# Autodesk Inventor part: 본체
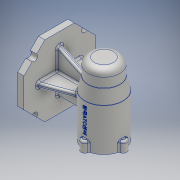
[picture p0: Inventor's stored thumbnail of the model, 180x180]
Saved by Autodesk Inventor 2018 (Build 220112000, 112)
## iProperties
Created: 2019-12
Part Number: 본체
Material: 알루미늄 6061
Document SubType Name: Modeling
Designer: Administrator
Density: 2.7 g/cm^3
Appearance: 알루미늄 - 평지
Mass: 726.009 g
Surface Area: 714.36 cm^2
Volume: 268.892 cm^3
Author: Administrator
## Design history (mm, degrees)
sketch "스케치1" dims "d0" = 112
  geometry: L1 (56, -23.196)-(23.196, -56); L2 (23.196, -56)-(-23.196, -56); L3 (-23.196, -56)-(-56, -23.196); L4 (-56, -23.196)-(-56, 23.196); L5 (-56, 23.196)-(-23.196, 56); L6 (-23.196, 56)-(23.196, 56); L7 (23.196, 56)-(56, 23.196); L8 (56, 23.196)-(56, -23.196); 5 further points
  constraints: 16 end point, 3 coincident, 1 horizontal alignment, 1 midpoint, 19 other
extrude "돌출1" new body sketch "스케치1" distance "d1" = 10; taper "d2" = 0 deg
sketch "스케치3"
  geometry: L1 (0, 0)-(-80, 0); L2 (-80, 0)-(-80, -56); L3 (-80, -56)-(-110, -56); L4 (-110, -56)-(-110, -40); L5 (-110, -40)-(-80, -40); L6 (-80, -40)-(-80, -56); L7 (-80, -40)-(-110, -40); L8 (-110, -40)-(-110, 11); L9 (-110, 11)-(-80, 11); L10 (-80, 11)-(-80, -40); L11 (-80, 0)-(-80, 56); L12 (-80, 56)-(-105, 56); L13 (-105, 56)-(-105, 31); L14 (-105, 31)-(-80, 31); L15 (-80, 31)-(-80, 56); L16 (-105, 31)-(-110, 11); L17 (-80, 31)-(-80, 11)
  constraints: 34 end point, 6 parallel, 4 horizontal, 3 perpendicular, 2 vertical, 1 point on line
  dimensions: "d4" = 56 distance of L1.end L2.end; "d5" = 30 distance of L4.end L5.end; "d6" = 16 distance of L3.end L4.end; "d7" = 30 distance of L8.end L9.end; "d8" = 51 distance of L7.end L8.end; "d9" = 56 distance of L1.end L11.end; "d10" = 25 distance of L14.end L13.end; "d11" = 25 distance of L13.end L12.end
revolve "회전1" sketch "스케치3" stored, may be unused: angle "d12" = 90 deg
sketch "스케치4"
  geometry: L1 (0, 0)-(0, 30); L2 (0, 30)-(0, -30); L3 (0, 0)-(-32.316, 0); L4 (-32.316, 0)-(30, 0); L5 (0, 0)-(-30, 0); L6 (-30, 0)-(30, 0); L7 (0, 0)-(-31.297, 0); C1 r 25 at (0, 0) reference; C2 r 6 at (-30, 0); C3 r 6 at (0, -30); C4 r 6 at (0, 30); C5 r 6 at (30, 0); A1 r 30 centre (0, 0) between (30, 0) and (0, 30); A2 r 30 centre (0, 0) between (0, 30) and (0, -30) reference; 1 further point
  constraints: 14 end point, 5 centre point, 5 point on circle, 4 coincident, 1 horizontal, 1 point on line, 1 vertical
  dimensions: "d13" = 12 diameter of C2; "d14" = 12 diameter of C3; "d15" = 12 diameter of C4; "d16" = 12 diameter of C5
extrude "돌출2" join sketch "스케치4" distance "d17" = 16; taper "d18" = 0 deg
sketch "스케치5"
  geometry: L1 (-10, -56)-(-10, -23.196) reference; L2 (-10, -56)-(-10, -31); L3 (-10, -31)-(-69.314, -31); L4 (-10, 23.196)-(-10, 56) reference; L5 (-10, 56)-(-10, 38); L6 (-10, 38)-(-71.6, 9.275); L7 (-71.6, 9.275)-(-69.314, -31); L8 (-10, -31)-(-10, 38); 1 further point
  constraints: 12 end point, 2 point on line, 1 collinear, 1 perpendicular
  dimensions: "d19" = 25 distance of L1.start L2.end; "d20" = 18 distance of L4.end L5.end; "d21" = 115 deg angle of L5 L6
extrude "돌출3" join sketch "스케치5" stored distance "d22" = 8; taper "d23" = 0 deg
node "작업 평면1"
sketch "스케치6"
  geometry: L1 (10, 79.196)-(10, 59.196); L2 (10, 46.392)-(10, 79.196) reference; L3 (10, -32.804)-(10, 0) reference; L4 (10, -32.804)-(10, -12.804); L5 (10, -12.804)-(64.681, 7.098); L6 (10, 59.196)-(75.807, 35.244); L7 (75.807, 35.244)-(64.681, 7.098); L8 (10, 59.196)-(10, -12.804); 1 further point
  constraints: 12 end point, 2 point on line, 1 collinear
  dimensions: "d24" = 20 distance of L1.start L1.end; "d25" = 20 distance of L3.start L4.end; "d26" = 110 deg angle of L4 L5; "d27" = 110 deg angle of L6 L1
extrude "돌출4" join sketch "스케치6" stored distance "d28" = 8; taper "d29" = 0 deg
sketch "스케치7"
  geometry: L1 (0, 0)-(-39.598, 39.598); L2 (0, 0)-(62.448, 0); L3 (0, 0)-(39.598, 39.598); L4 (0, 0)-(80.362, 0); L5 (0, 0)-(39.598, -39.598); L6 (0, 0)-(85.885, 0); L7 (0, 0)-(-39.598, -39.598); L8 (0, 0)-(72.456, 0); L9 (-56, 23.196)-(-23.196, 56) reference; L10 (-56, 23.196)-(-23.196, 56); L11 (-23.196, 56)-(23.196, 56); L12 (23.196, 56)-(56, 23.196); L13 (56, 23.196)-(56, -23.196); L14 (56, -23.196)-(23.196, -56); L15 (23.196, -56)-(-23.196, -56); L16 (-23.196, -56)-(-56, -23.196); L17 (-56, -23.196)-(-56, 23.196); 1 further point
  constraints: 32 end point, 4 horizontal, 4 midpoint, 1 coincident, 17 other
  dimensions: "d30" = 135 deg angle of L2 L1; "d31" = 45 deg angle of L4 L3; "d32" = 45 deg angle of L5 L6; "d33" = 135 deg angle of L7 L8
hole "구멍1" sketch "스케치7" at (39.598, 39.598), (-39.598, -39.598), (39.598, -39.598), (-39.598, 39.598) diameter "d34" = 10; stored, may be unused: countersink angle "d38" = 90 deg, drill point angle "d40" = 118 deg; dims "d35" = 6, "d36" = 4, "d37" = 2, "d39" = 10
sketch "스케치8"
  geometry: L1 (-74, -56)-(-86, -56) reference; L2 (-80, -56)-(-101, -56); L3 (-101, -56)-(-101, -41); L4 (-101, -41)-(-80, -41); L5 (-80, -41)-(-80, -56); L6 (-80, -41)-(-104, -41); L7 (-104, -41)-(-104, 13); L8 (-104, 13)-(-80, 13); L9 (-80, 13)-(-80, -41); L10 (-80, 13)-(-101, 13); L11 (-101, 13)-(-101, 25); L12 (-101, 25)-(-80, 25); L13 (-80, 25)-(-80, 13); L14 (-80, 25)-(-97.5, 25); L15 (-97.5, 25)-(-97.5, 43); L16 (-97.5, 43)-(-80, 43); L17 (-80, 43)-(-80, 25); L18 (-80, 43)-(-96, 43); L19 (-96, 43)-(-96, 47); L20 (-96, 47)-(-80, 47); L21 (-80, 47)-(-80, 43); L22 (-80, 47)-(-90.5, 47); L23 (-90.5, 47)-(-90.5, 50); L24 (-90.5, 50)-(-80, 50); L25 (-80, 50)-(-80, 47); 3 further points
  constraints: 48 end point, 12 parallel, 6 horizontal, 6 perpendicular, 1 midpoint
  dimensions: "d41" = 21 distance of L3.end L4.end; "d42" = 15 distance of L2.end L3.end; "d43" = 24 distance of L7.end L8.end; "d44" = 54 distance of L6.end L7.end; "d45" = 21 distance of L11.end L12.end; "d46" = 12 distance of L10.end L11.end; "d47" = 17.5 distance of L15.end L16.end; "d48" = 18 distance of L14.end L15.end; "d49" = 16 distance of L19.end L20.end; "d50" = 4 distance of L18.end L19.end; "d51" = 10.5 distance of L23.end L24.end; "d52" = 3 distance of L22.end L23.end
revolve "회전2" sketch "스케치8" stored, may be unused: angle "d53" = 90 deg
fillet "모깎기1" dims "d54" = 3
fillet "모깎기2" dims "d55" = 0.3
fillet "모깎기3" dims "d56" = 3
chamfer "모따기1" distance "d57" = 1; stored, may be unused: second distance "d58" = 2, angle "d59" = 45 deg
fillet "모깎기4" dims "d60" = 10
fillet "모깎기5" dims "d61" = 3
fillet "모깎기6" dims "d62" = 3
fillet "모깎기7" dims "d63" = 1
fillet "모깎기8" dims "d64" = 3
fillet "모깎기9" dims "d65" = 3
fillet "모깎기10" dims "d66" = 3
fillet "모깎기11" dims "d67" = 3
sketch "스케치10"
  geometry: L1 (0, -30)-(-30, -30); L2 (-30, -30)-(30, -30); L3 (0, -30)-(0, 0); L4 (0, 0)-(0, -60); C1 r 22 at (0, -30) reference; A1 r 30 centre (0, -30) between (0, -60) and (-30, -30); 1 further point
  constraints: 8 end point, 4 point on circle, 1 centre point, 1 coincident, 1 horizontal, 1 vertical
  dimensions: "d68" = 60 diameter of A1
hole "구멍2" sketch "스케치10" at (0, -60), (-30, -30), (0, 0), (30, -30) diameter "d69" = 3.242; stored, may be unused: countersink angle "d73" = 90 deg, drill point angle "d75" = 118 deg; dims "d70" = 8, "d71" = 4, "d72" = 2, "d74" = 11
node "작업 평면2"
node "작업 평면3"
sketch "스케치13"
  geometry: 1 further point
node "작업 평면4"
node "작업 평면5"
sketch "스케치14"
  geometry: L1 (-22, -8)-(22, -8) reference; 2 further points
  constraints: 1 other
feature "엠보싱1" sketch "스케치14" dims "d0" = 112, "d4" = 56, "d5" = 30, "d6" = 16, "d7" = 30, "d8" = 51, "d9" = 56, "d10" = 25, "d11" = 25, "d78" = 0.5, "d79" = 0
node "솔리드1"
